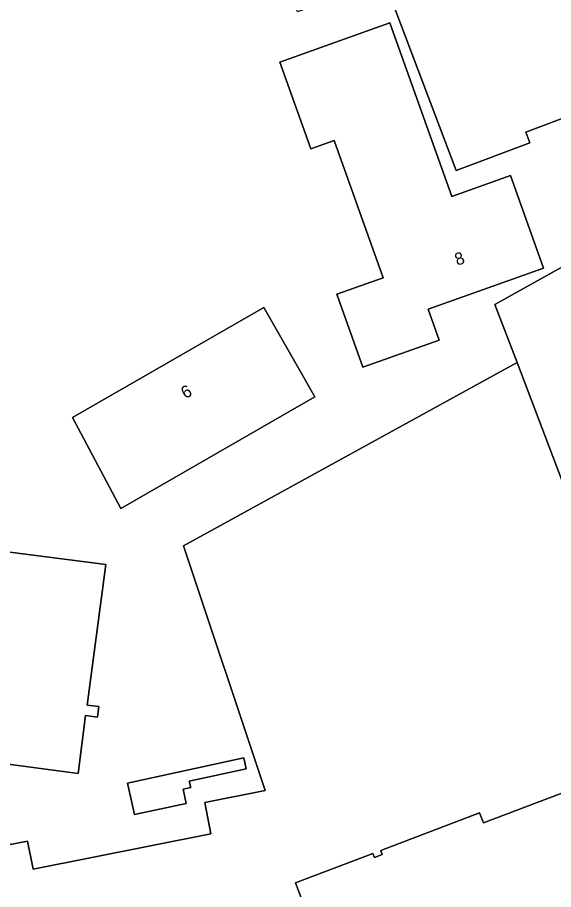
# Model space of a CAD drawing. Extents: x 160023 to 161302, y 384750 to 385707.
# Drawn here: x 160742 to 160785.6, y 384880 to 384950.8 of the extents above; entities that cross this region are included whole.
import ezdxf

# ---------------------------------------------------------------- set-up
doc = ezdxf.new("R2010")
doc.units = 0
for name, color, linetype in [('IMGEO_Erf', 7, 'Continuous'), ('IMGEO_Pand', 7, 'Continuous'), ('IMGEO_Pand_nummerreeks', 7, 'Continuous')]:
    doc.layers.add(name, color=color, linetype=linetype)

msp = doc.modelspace()

# ---------------------------------------------------------------- linework, layer by layer
at = {"layer": 'IMGEO_Erf'}
for points in [[(160802.073, 384936.28), (160801.225, 384938.495), (160806.645, 384940.552), (160809.45, 384941.617), (160808.778, 384943.448), (160806.014, 384942.433), (160798.704, 384939.75), (160797.519, 384942.884), (160801.811, 384944.506), (160800.498, 384947.981), (160799.934, 384947.768), (160783.304, 384941.484), (160783.627, 384940.629), (160777.651, 384938.371), (160771.783, 384953.899), (160769.455, 384953.019), (160764.777, 384951.251), (160757.299, 384977.06), (160751.717, 384978), (160740.511, 384980.552)], [(160736.144, 384869.451), (160733.533, 384882.133), (160738.872, 384883.188), (160742.841, 384883.972), (160743.29, 384881.699), (160757.729, 384884.553), (160757.227, 384887.095), (160762.126, 384888.063), (160755.507, 384907.922), (160782.595, 384922.812), (160780.796, 384927.511), (160781.023, 384927.638), (160794.809, 384935.33), (160795.485, 384933.758), (160802.073, 384936.28)], [(160798.942, 384878.251), (160797.112, 384883.06), (160791.384, 384881.395), (160790.112, 384884.737), (160788.586, 384888.745), (160779.859, 384885.441), (160779.549, 384886.257), (160771.521, 384883.201), (160771.642, 384882.873), (160771.014, 384882.635), (160770.893, 384882.963), (160764.6, 384880.569), (160766.456, 384875.692)]]:
    msp.add_lwpolyline(points, dxfattribs=at)
for points in [[(160784.732, 384930.464), (160775.379, 384927.123), (160776.271, 384924.625), (160770.071, 384922.41), (160767.954, 384928.339), (160771.72, 384929.683), (160767.746, 384940.812), (160765.85, 384940.135), (160763.339, 384947.165), (160772.272, 384950.355), (160777.301, 384936.272), (160782.051, 384937.969)], [(160764.517, 384922.917), (160766.178, 384920.019), (160754.749, 384913.454), (160750.413, 384910.963), (160746.496, 384918.348), (160762.03, 384927.254)], [(160738.42, 384907.796), (160749.186, 384906.408), (160747.691, 384895.001), (160748.642, 384894.876), (160748.529, 384894.017), (160747.56, 384894.144), (160746.946, 384889.455), (160741.667, 384890.147), (160736.709, 384890.797), (160736.783, 384891.361), (160731.693, 384892.028), (160731.63, 384891.54), (160731.121, 384891.606), (160731.893, 384897.495), (160732.44, 384897.423), (160733.808, 384907.961), (160733.408, 384908.01), (160733.456, 384908.398)], [(160760.399, 384890.709), (160760.59, 384889.822), (160755.977, 384888.828), (160756.09, 384888.307), (160755.467, 384888.172), (160755.715, 384887.021), (160751.516, 384886.116), (160750.965, 384888.676)]]:
    msp.add_lwpolyline(points, close=True, dxfattribs=at)
at = {"layer": 'IMGEO_Pand'}
for points in [[(160809.153, 384951.006), (160809.836, 384951.265), (160806.264, 384960.926), (160806.623, 384961.06), (160804.929, 384965.751), (160804.882, 384965.734), (160804.693, 384966.267), (160771.783, 384953.899), (160777.651, 384938.371), (160783.627, 384940.629), (160783.304, 384941.484), (160799.934, 384947.768), (160799.812, 384948.089), (160808.95, 384951.552)], [(160772.272, 384950.355), (160763.339, 384947.165), (160765.85, 384940.135), (160767.746, 384940.812), (160771.72, 384929.683), (160767.954, 384928.339), (160770.071, 384922.41), (160776.271, 384924.625), (160775.379, 384927.123), (160784.732, 384930.464), (160782.051, 384937.969), (160777.301, 384936.272)], [(160796.441, 384928.208), (160797.46, 384928.598), (160795.485, 384933.758), (160794.809, 384935.33), (160781.023, 384927.638), (160780.796, 384927.511), (160782.595, 384922.812), (160786.39, 384912.828), (160795.775, 384916.421), (160801.754, 384918.71), (160800.004, 384923.282), (160798.542, 384922.722)], [(160754.749, 384913.454), (160766.178, 384920.019), (160764.517, 384922.917), (160762.03, 384927.254), (160746.496, 384918.348), (160750.413, 384910.963)], [(160788.586, 384888.745), (160794.298, 384890.791), (160790.532, 384901.978), (160787.477, 384909.982), (160786.39, 384912.828), (160782.595, 384922.812), (160755.507, 384907.922), (160762.126, 384888.063), (160757.227, 384887.095), (160757.729, 384884.553), (160743.29, 384881.699), (160742.841, 384883.972), (160738.872, 384883.188), (160733.533, 384882.133), (160736.144, 384869.451), (160741.042, 384870.459), (160766.456, 384875.692), (160764.6, 384880.569), (160770.893, 384882.963), (160771.014, 384882.635), (160771.642, 384882.873), (160771.521, 384883.201), (160779.549, 384886.257), (160779.859, 384885.441)], [(160733.456, 384908.398), (160733.408, 384908.01), (160733.808, 384907.961), (160732.44, 384897.423), (160731.893, 384897.495), (160731.121, 384891.606), (160731.63, 384891.54), (160731.693, 384892.028), (160736.783, 384891.361), (160736.709, 384890.797), (160741.667, 384890.147), (160746.946, 384889.455), (160747.56, 384894.144), (160748.529, 384894.017), (160748.642, 384894.876), (160747.691, 384895.001), (160749.186, 384906.408), (160738.42, 384907.796)], [(160760.399, 384890.709), (160750.965, 384888.676), (160751.516, 384886.116), (160755.715, 384887.021), (160755.467, 384888.172), (160756.09, 384888.307), (160755.977, 384888.828), (160760.59, 384889.822)]]:
    msp.add_lwpolyline(points, close=True, dxfattribs=at)

# ---------------------------------------------------------------- texts
at = {"layer": 'IMGEO_Pand_nummerreeks'}
for s, rotation, p in [('8', 19.65818, (160777.738, 384930.642)), ('6', 29.82664, (160755.655, 384919.819))]:
    msp.add_text(s, height=1, rotation=rotation, dxfattribs=at).set_placement(p)

doc.saveas('drawing.dxf')
